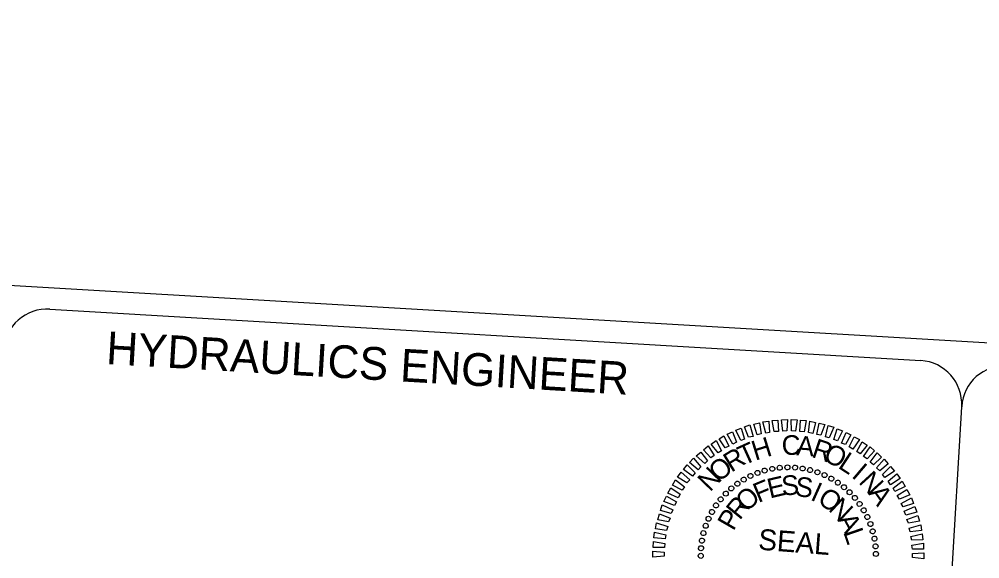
# Model space of a CAD drawing. Extents: x 1998567 to 2027801, y 439108 to 451079.
# Drawn here: x 2016563 to 2018763, y 440872 to 442108 of the extents above; entities that cross this region are included whole.
import ezdxf

# ---------------------------------------------------------------- set-up
doc = ezdxf.new("R2010")
doc.units = 0
doc.layers.add('Sheet Professional Seal CELL', color=7, linetype='Continuous')
doc.layers.add('Sheet Title CELL', color=7, linetype='Continuous')

msp = doc.modelspace()

# ---------------------------------------------------------------- linework, layer by layer
at = {"layer": 'Sheet Professional Seal CELL'}
for p, q in [((2018287.6, 441077.9), (2018287.6, 441077.9)), ((2018305.4, 441080.1), (2018305.4, 441080.1)), ((2018322.7, 441081.5), (2018322.7, 441081.5)), ((2018340.3, 441080.8), (2018340.3, 441080.8)), ((2018357.8, 441078.6), (2018357.8, 441078.6)), ((2018238.2, 441061.6), (2018238.2, 441061.6)), ((2018254.2, 441068.7), (2018254.2, 441068.7)), ((2018270.6, 441074.1), (2018270.6, 441074.1)), ((2018374.8, 441074.8), (2018374.8, 441074.8)), ((2018391.3, 441070.2), (2018391.3, 441070.2)), ((2018407.8, 441063.6), (2018407.8, 441063.6)), ((2018207.9, 441044.2), (2018207.9, 441044.2)), ((2018222.5, 441053.3), (2018222.5, 441053.3)), ((2018423.3, 441055.5), (2018423.3, 441055.5)), ((2018438.4, 441046.6), (2018438.4, 441046.6)), ((2018452.2, 441035.8), (2018452.2, 441035.8)), ((2018181.3, 441021.3), (2018181.3, 441021.3)), ((2018194, 441033), (2018194, 441033)), ((2018465.6, 441024.2), (2018465.6, 441024.2)), ((2018158.9, 440994.2), (2018158.9, 440994.2)), ((2018169.7, 441007.9), (2018169.7, 441007.9)), ((2018477.2, 441011.5), (2018477.2, 441011.5)), ((2018488.4, 440997.6), (2018488.4, 440997.6)), ((2018150, 440979.1), (2018150, 440979.1)), ((2018497.6, 440983), (2018497.6, 440983)), ((2018135.3, 440947.1), (2018135.3, 440947.1)), ((2018141.8, 440963.5), (2018141.8, 440963.5)), ((2018505.9, 440967.3), (2018505.9, 440967.3)), ((2018513, 440951.2), (2018513, 440951.2)), ((2018130.7, 440930.5), (2018130.7, 440930.5)), ((2018518.4, 440934.9), (2018518.4, 440934.9)), ((2018126.9, 440913.5), (2018126.9, 440913.5)), ((2018522.2, 440917.8), (2018522.2, 440917.8)), ((2018124.6, 440896), (2018124.6, 440896)), ((2018324.9, 440880.6), (2018324.9, 440880.6)), ((2018524.4, 440900.1), (2018524.4, 440900.1)), ((2018525.7, 440882.8), (2018525.7, 440882.8)), ((2018124, 440878.4), (2018124, 440878.4))]:
    msp.add_line(p, q, dxfattribs=at)
for points in [[(2018292.6, 441163), (2018287.8, 441188.9), (2018301, 441189.3), (2018302.3, 441163.6)], [(2018311.9, 441164.2), (2018309.1, 441190.1), (2018322.7, 441190.9), (2018321.6, 441164.9)], [(2018332, 441165.1), (2018331.6, 441191.1), (2018344.7, 441190), (2018341.6, 441164.1)], [(2018351.2, 441163.5), (2018352.7, 441189.5), (2018365.9, 441188.3), (2018360.7, 441162.6)], [(2018215.7, 441143.1), (2018204.3, 441166.2), (2018217, 441171), (2018224.7, 441146.1)], [(2018233.8, 441150.4), (2018224.8, 441174.2), (2018237, 441178.3), (2018243.9, 441152.2)], [(2018253.7, 441155.7), (2018246, 441180.2), (2018258.6, 441183), (2018262.3, 441158)], [(2018273.2, 441159.7), (2018266.3, 441185.4), (2018280, 441187.4), (2018281.7, 441161.2)], [(2018371.1, 441161.2), (2018374.2, 441187), (2018387.2, 441183.8), (2018380.6, 441159)], [(2018390, 441156.8), (2018395.1, 441182.2), (2018408.2, 441179.4), (2018399.6, 441155.1)], [(2018410.1, 441151.2), (2018415.7, 441177), (2018429.1, 441173), (2018418.4, 441148.8)], [(2018429, 441144.9), (2018436.5, 441169.3), (2018448.6, 441164.6), (2018437.2, 441141.6)], [(2018179.8, 441125.6), (2018166.3, 441146.8), (2018177.1, 441153.8), (2018188.9, 441129.8)], [(2018198, 441134.5), (2018184.5, 441156.9), (2018197.2, 441162.6), (2018205.9, 441138.8)], [(2018446.6, 441136.7), (2018457.2, 441161.3), (2018468.1, 441155.8), (2018455.6, 441133.3)], [(2018464.1, 441128), (2018475.4, 441151), (2018487.5, 441144.7), (2018472.6, 441123.1)], [(2018147.3, 441103), (2018130.7, 441121.6), (2018140.9, 441130.7), (2018155.2, 441108.2)], [(2018164, 441114.5), (2018147.9, 441134.6), (2018159.2, 441142.4), (2018171.8, 441119.2)], [(2018481.9, 441117.8), (2018494, 441139.9), (2018505.6, 441132.4), (2018489.2, 441112.5)], [(2018496.8, 441106.1), (2018512.2, 441128.4), (2018522.1, 441119.4), (2018505.3, 441100.8)], [(2018118.4, 441075.5), (2018098.5, 441092.3), (2018107.9, 441102.1), (2018124.4, 441082.3)], [(2018133.3, 441089.8), (2018113.9, 441107.4), (2018124.4, 441116), (2018140, 441095.8)], [(2018512.5, 441093.1), (2018528.6, 441114.2), (2018538.4, 441104.8), (2018519.8, 441087.1)], [(2018105.5, 441061), (2018084.7, 441075.9), (2018093, 441087), (2018111.1, 441068.3)], [(2018526.9, 441079.8), (2018544.5, 441099.6), (2018553.6, 441089.5), (2018534.2, 441073.4)], [(2018540.5, 441065), (2018558.8, 441082.8), (2018567.8, 441072.6), (2018546.1, 441058.3)], [(2018092.6, 441045.7), (2018070.9, 441059), (2018079.6, 441069.8), (2018099.4, 441052.6)], [(2018553.6, 441049.8), (2018573.1, 441066.7), (2018580.8, 441055.4), (2018558.7, 441041.5)], [(2018072.9, 441011.2), (2018048.7, 441021.9), (2018055.4, 441033.9), (2018077.4, 441019.8)], [(2018082, 441029.1), (2018059.8, 441040.5), (2018066.5, 441052.5), (2018087.2, 441036.4)], [(2018564.7, 441033.5), (2018585.2, 441049.2), (2018592.1, 441037.1), (2018569, 441025.7)], [(2018063.9, 440994.1), (2018039.6, 441002.8), (2018045.5, 441014.9), (2018068.8, 441002.3)], [(2018574.1, 441016.6), (2018596.2, 441030.5), (2018603, 441018.1), (2018579.2, 441008.2)], [(2018056.8, 440975.3), (2018032.3, 440982), (2018035.9, 440995), (2018060.5, 440983.5)], [(2018583.5, 440998.4), (2018606.6, 441011), (2018611.1, 440998.4), (2018587.8, 440990.5)], [(2018590.4, 440980.7), (2018614.7, 440991.3), (2018619.1, 440978.2), (2018593.9, 440971.7)], [(2018050.5, 440956.5), (2018025.9, 440961.1), (2018029.5, 440974.5), (2018054.2, 440964.7)], [(2018596.5, 440961.5), (2018621.5, 440970.5), (2018625.1, 440957.9), (2018600, 440952.9)], [(2018046.1, 440936.3), (2018020.7, 440940.2), (2018023.1, 440953.7), (2018048.6, 440945.8)], [(2018601.8, 440942), (2018627.9, 440949.7), (2018629.5, 440936.4), (2018604.1, 440933.5)], [(2018042.9, 440917.2), (2018017, 440919.6), (2018018.6, 440932.7), (2018044.3, 440926.8)], [(2018605.4, 440922.6), (2018631, 440928.7), (2018632.6, 440914.9), (2018607.3, 440914)], [(2018041.4, 440897.3), (2018015.3, 440897.6), (2018016.1, 440911.2), (2018041.9, 440906.9)], [(2018607.9, 440903.2), (2018634.2, 440907.2), (2018634.6, 440893.6), (2018608.9, 440893.5)], [(2018040.6, 440877.3), (2018014.4, 440875.7), (2018014.4, 440889.3), (2018040.4, 440886.9)], [(2018609.2, 440883.9), (2018635.3, 440885.5), (2018635.3, 440871.9), (2018609.4, 440874.2)]]:
    msp.add_lwpolyline(points, close=True, dxfattribs=at)
for centre, major_axis in [((2018270.8, 441073.8), (-1.55, 5.55)), ((2018287.9, 441077.8), (-1.06, 5.66)), ((2018305.2, 441080.3), (-0.56, 5.73)), ((2018322.7, 441081.2), (-0.06, 5.76)), ((2018340.2, 441080.6), (0.44, 5.74)), ((2018357.6, 441078.6), (0.94, 5.68)), ((2018374.7, 441075), (1.43, 5.58)), ((2018222.7, 441053.2), (-2.93, 4.96)), ((2018238.1, 441061.5), (-2.49, 5.19)), ((2018254.2, 441068.4), (-2.03, 5.39)), ((2018391.4, 441069.9), (1.91, 5.43)), ((2018407.7, 441063.4), (2.38, 5.25)), ((2018423.3, 441055.4), (2.83, 5.02)), ((2018194.2, 441032.9), (-3.75, 4.37)), ((2018208, 441043.7), (-3.36, 4.68)), ((2018438.2, 441046.2), (3.25, 4.75)), ((2018452.2, 441035.7), (3.65, 4.45)), ((2018169.8, 441007.9), (-4.45, 3.65)), ((2018181.5, 441020.9), (-4.12, 4.03)), ((2018465.2, 441024), (4.03, 4.12)), ((2018477.2, 441011.2), (4.37, 3.75)), ((2018159.3, 440993.9), (-4.75, 3.25)), ((2018488, 440997.5), (4.68, 3.36)), ((2018142.1, 440963.4), (-5.25, 2.38)), ((2018150, 440979), (-5.02, 2.83)), ((2018497.5, 440982.8), (4.96, 2.93)), ((2018505.8, 440967.4), (5.19, 2.49)), ((2018135.6, 440947.2), (-5.43, 1.91)), ((2018512.7, 440951.3), (5.39, 2.03)), ((2018130.5, 440930.4), (-5.58, 1.43)), ((2018518.1, 440934.6), (5.55, 1.55)), ((2018522.1, 440917.6), (5.66, 1.06)), ((2018124.8, 440895.9), (-5.74, 0.44)), ((2018126.9, 440913.3), (-5.68, 0.94)), ((2018524.5, 440900.3), (5.73, 0.56)), ((2018124.2, 440878.4), (-5.76, -0.06)), ((2018525.5, 440882.8), (5.76, 0.06))]:
    msp.add_ellipse(centre, major_axis=major_axis, ratio=0.999708, dxfattribs=at)
at = {"layer": 'Sheet Title CELL'}
for p, q in [((2006204.7, 442108.3), (2020380.1, 441272.7)), ((2016633.6, 441443.5), (2018627.9, 441325.9)), ((2018627.7, 439623), (2018721.8, 441220.2))]:
    msp.add_line(p, q, dxfattribs=at)
for centre, start, end in [((2016627.8, 441344.1), 86.6264, 176.6264), ((2018622, 441226.1), 356.6264, 86.6264), ((2018821.7, 441214.3), 86.6264, 176.6264)]:
    msp.add_arc(centre, 100, start, end, dxfattribs=at)

# ---------------------------------------------------------------- texts
at = {"layer": 'Sheet Professional Seal CELL'}
for s, height, rotation, p in [('H', 45.1, 17.2459, (2018249, 441096.2)), ('C', 45.1, 2.8463, (2018310.7, 441108.6)), ('A', 45.1, 355.6467, (2018342.4, 441109.2)), ('R', 45.1, 341.2475, (2018375.8, 441105.6)), ('R', 45.1, 31.6469, (2018194.1, 441068.6)), ('T', 45.1, 24.4462, (2018222.3, 441084.6)), ('O', 45.1, 334.0476, (2018402.2, 441098)), ('O', 45.1, 38.8482, (2018165.1, 441045.5)), ('L', 45.1, 326.8473, (2018436.5, 441081.2)), ('N', 45.1, 46.0499, (2018145.4, 441023.4)), ('I', 45.1, 319.6466, (2018467.7, 441060.1)), ('E', 45.1, 13.2375, (2018282.4, 441009.7)), ('S', 45.1, 3.882, (2018310.4, 441016.5)), ('S', 45.1, 354.5268, (2018339.2, 441015.2)), ('N', 45.1, 312.4453, (2018484.1, 441046.7)), ('F', 45.1, 22.5935, (2018256.1, 440999.2)), ('I', 45.1, 335.816, (2018373.2, 441007.6)), ('A', 45.1, 305.2436, (2018506.3, 441021.8)), ('R', 45.1, 50.6661, (2018213.3, 440958.5)), ('O', 45.1, 41.3077, (2018228.4, 440977.2)), ('O', 45.1, 326.4599, (2018388.9, 441001)), ('N', 45.1, 317.103, (2018414.7, 440983.5)), ('P', 45.1, 60.0253, (2018199, 440933.7)), ('A', 45.1, 298.3867, (2018436.2, 440961.4)), ('SEAL', 47.99, 355.6264, (2018254.7, 440892.7)), ('L', 45.1, 289.0273, (2018450.2, 440932.9))]:
    msp.add_text(s, height=height, rotation=rotation, dxfattribs=at).set_placement(p)
at = {"layer": 'Sheet Title CELL'}
msp.add_text(' HYDRAULICS ENGINEER', height=75, rotation=356.6264, dxfattribs=at).set_placement((2016733.5, 441319.7))

doc.saveas('drawing.dxf')
